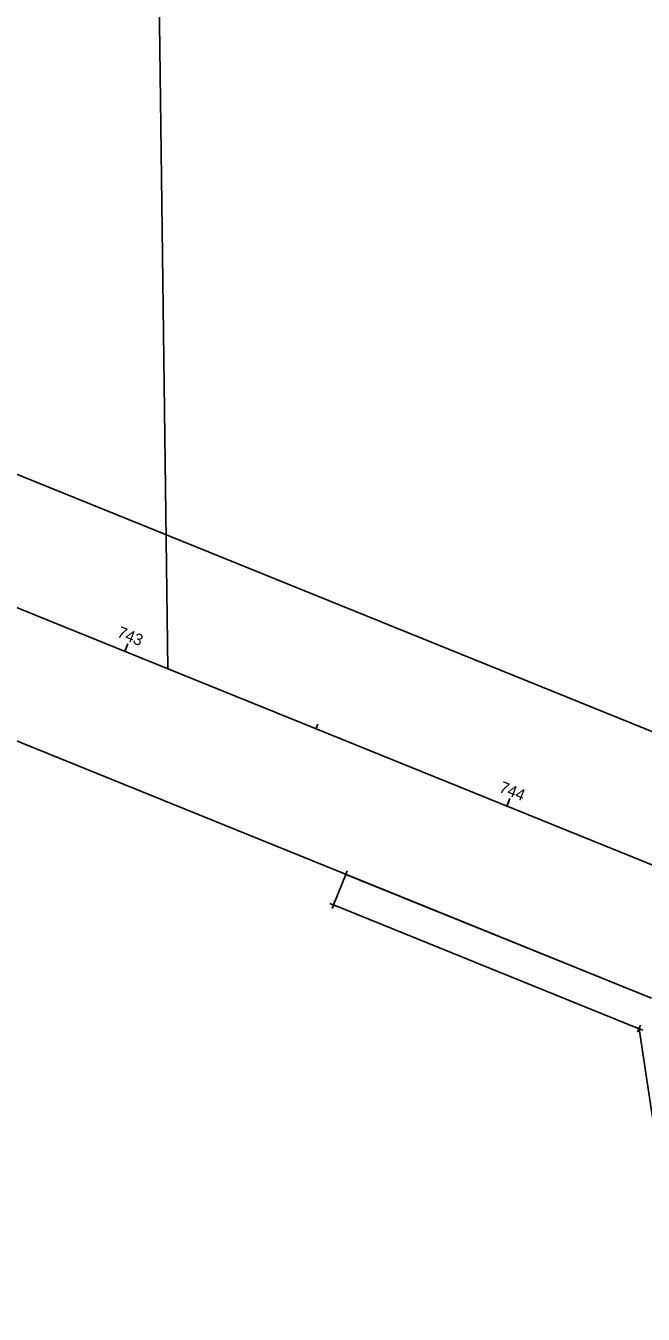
# Model space of a CAD drawing. Extents: x 2345526 to 2352057, y 624934 to 629976.
# Drawn here: x 2347057.2 to 2347207, y 627418.4 to 627730.9 of the extents above; entities that cross this region are included whole.
import ezdxf

# ---------------------------------------------------------------- set-up
doc = ezdxf.new("R2010")
doc.units = 0
for name, color, linetype in [('DT_X_TIN_Hull', 7, 'Continuous'), ('RW_P_Esmt_SH', 7, 'Continuous'), ('RW_P_Esmt_TMP', 7, 'Continuous'), ('RW_X_CL', 7, 'Continuous'), ('RW_X_CL_100_Cardinal_Points', 7, 'Continuous'), ('RW_X_CL_500_Cardinal_Points', 7, 'Continuous'), ('RW_X_Esmt_SH', 7, 'Continuous')]:
    doc.layers.add(name, color=color, linetype=linetype)

msp = doc.modelspace()

# ---------------------------------------------------------------- linework, layer by layer
at = {"layer": 'DT_X_TIN_Hull'}
for p, q in [((2347131.88, 627517.66), (2347134.88, 627525.08)), ((2347134.01, 627525.43), (2347135.76, 627524.72)), ((2347134.53, 627524.2), (2347135.23, 627525.95)), ((2347134.88, 627525.08), (2347209.04, 627495.06)), ((2347131.01, 627518.02), (2347132.75, 627517.31)), ((2347131.53, 627516.79), (2347132.23, 627518.54)), ((2347206.04, 627487.65), (2347131.88, 627517.66)), ((2347205.16, 627488), (2347206.91, 627487.29)), ((2347205.68, 627486.77), (2347206.39, 627488.52)), ((2347209.83, 627462.38), (2347206.04, 627487.65))]:
    msp.add_line(p, q, dxfattribs=at)
at = {"layer": 'RW_P_Esmt_SH'}
for p, q in [((2347134.88, 627525.08), (2347131.88, 627517.66)), ((2347131.88, 627517.66), (2347206.04, 627487.65)), ((2347206.04, 627487.65), (2347209.83, 627462.38))]:
    msp.add_line(p, q, dxfattribs=at)
at = {"layer": 'RW_P_Esmt_TMP'}
msp.add_line((2347091.7, 627574.92), (2347063.32, 629798.91), dxfattribs=at)
at = {"layer": 'RW_X_CL'}
msp.add_line((2345617.75, 628171.49), (2348868.68, 626855.7), dxfattribs=at)
at = {"layer": 'RW_X_CL_100_Cardinal_Points'}
for p, q in [((2347081.25, 627579.15), (2347082, 627581)), ((2347127.6, 627560.39), (2347128.05, 627561.5)), ((2347173.95, 627541.63), (2347174.7, 627543.49))]:
    msp.add_line(p, q, dxfattribs=at)
at = {"layer": 'RW_X_CL_500_Cardinal_Points'}
for p, q in [((2347081.25, 627579.15), (2347081.7, 627580.26)), ((2347173.95, 627541.63), (2347174.4, 627542.74))]:
    msp.add_line(p, q, dxfattribs=at)
at = {"layer": 'RW_X_Esmt_SH'}
for p, q in [((2346860.77, 627700.75), (2347555.98, 627419.37)), ((2346838.26, 627645.14), (2347209.04, 627495.06))]:
    msp.add_line(p, q, dxfattribs=at)

# ---------------------------------------------------------------- texts
at = {"layer": 'RW_X_CL_100_Cardinal_Points'}
for s, p in [('743', (2347079.18, 627582.74)), ('744', (2347171.88, 627545.16))]:
    msp.add_text(s, height=2.8, rotation=337.9647, dxfattribs=at).set_placement(p)

doc.saveas('drawing.dxf')
